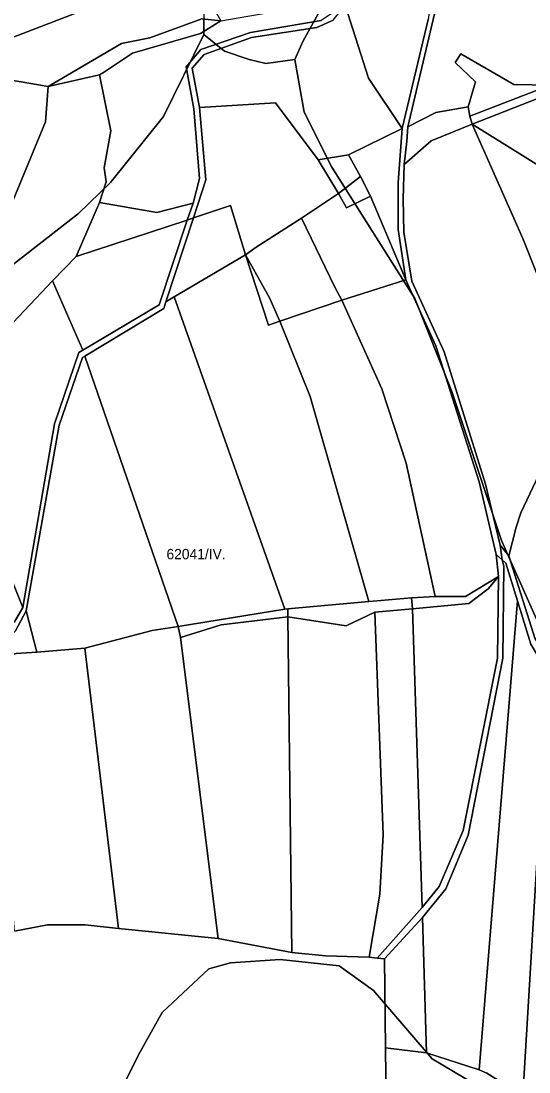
# Model space of a CAD drawing. Extents: x -521261 to -517465, y -1182764 to -1179456.
# Drawn here: x -519763 to -519518, y -1182060 to -1181552 of the extents above; entities that cross this region are included whole.
import ezdxf

# ---------------------------------------------------------------- set-up
doc = ezdxf.new("R2010")
doc.units = 0
for name, color, linetype in [('95560013', 7, 'Continuous'), ('95610013', 7, 'Continuous'), ('95640013', 7, 'Continuous'), ('95660013', 7, 'Continuous')]:
    doc.layers.add(name, color=color, linetype=linetype)

msp = doc.modelspace()

# ---------------------------------------------------------------- linework, layer by layer
at = {"layer": '95560013'}
for points in [[(-519680.38, -1181522.18), (-519678.62, -1181526.13), (-519766.59, -1181560.03), (-519806.34, -1181557.48), (-519812.18, -1181559.97), (-519819.03, -1181562.34), (-519820.94, -1181549.11), (-519799.35, -1181551.07), (-519780.96, -1181551.7), (-519759.56, -1181546.55), (-519747.84, -1181543.58), (-519734.21, -1181538), (-519696.97, -1181527.88)], [(-519679.91, -1181647.56), (-519662.1, -1181641.54), (-519654.76, -1181665.48), (-519689.23, -1181685.68), (-519693.3, -1181688.1)], [(-519679.91, -1181647.56), (-519693.3, -1181688.1), (-519694.25, -1181691.29), (-519732.44, -1181714.35), (-519733.56, -1181715), (-519744.8, -1181747.67), (-519760.86, -1181837.52), (-519766.01, -1181847.11), (-519783.93, -1181864.52), (-519787.23, -1181865.65), (-519792.03, -1181867.82), (-519766.42, -1181842.85), (-519762.47, -1181835.83), (-519747.07, -1181747.06), (-519735.36, -1181712.66), (-519733.42, -1181711.55), (-519696.55, -1181689.51), (-519683.02, -1181648.68)], [(-519683.02, -1181648.68), (-519696.55, -1181689.51), (-519733.42, -1181711.55), (-519748.09, -1181677.97), (-519736.69, -1181666.21)], [(-519654.76, -1181665.48), (-519643.73, -1181699.41), (-519638.17, -1181697.44), (-519623.58, -1181733.81), (-519595.24, -1181832.9), (-519634.35, -1181836.49), (-519635.8, -1181836.66), (-519689.23, -1181685.68)], [(-519748.09, -1181677.97), (-519733.42, -1181711.55), (-519735.36, -1181712.66), (-519747.07, -1181747.06), (-519762.47, -1181835.83), (-519785.74, -1181777.95), (-519807.95, -1181734.53), (-519769.78, -1181700.98)], [(-519608.18, -1181687.27), (-519577.34, -1181677.47), (-519562.88, -1181709.42), (-519541.79, -1181775.11), (-519533.67, -1181810.31), (-519532.44, -1181820.87), (-519548.5, -1181830.55), (-519563.13, -1181830.46), (-519577.15, -1181766.06), (-519588.95, -1181730.16)], [(-519689.23, -1181685.68), (-519635.8, -1181836.66), (-519687.27, -1181844.99), (-519732.44, -1181714.35), (-519694.25, -1181691.29), (-519693.3, -1181688.1)], [(-519638.17, -1181697.44), (-519608.18, -1181687.27), (-519588.95, -1181730.16), (-519577.15, -1181766.06), (-519563.13, -1181830.46), (-519574.5, -1181831.25), (-519593.02, -1181832.73), (-519595.24, -1181832.9), (-519623.58, -1181733.81)], [(-519733.56, -1181715), (-519732.44, -1181714.35), (-519687.27, -1181844.99), (-519699.9, -1181846.96), (-519732.49, -1181855.46), (-519755.59, -1181857.41), (-519760.86, -1181837.52), (-519744.8, -1181747.67)], [(-519807.95, -1181734.53), (-519785.74, -1181777.95), (-519762.47, -1181835.83), (-519766.42, -1181842.85), (-519792.03, -1181867.82), (-519816.1, -1181875.42), (-519863.92, -1181760.51)], [(-519530.74, -1181812.82), (-519530, -1181815.87), (-519530.37, -1181860.39), (-519547.1, -1181945.82), (-519558, -1181971.8), (-519569.21, -1181985.7), (-519587.58, -1182005.62), (-519591.13, -1182005.4), (-519569.48, -1181980.84), (-519561.19, -1181970.73), (-519549.62, -1181943.63), (-519533.07, -1181860.26), (-519532.44, -1181820.87), (-519533.67, -1181810.31)], [(-519529.03, -1181814.46), (-519523.41, -1181832.63), (-519541.91, -1182059.26), (-519567.33, -1182051.07), (-519569.21, -1181985.7), (-519558, -1181971.8), (-519547.1, -1181945.82), (-519530.37, -1181860.39), (-519530, -1181815.87), (-519530.74, -1181812.82)], [(-519532.44, -1181820.87), (-519537.44, -1181826.81), (-519546.83, -1181833.97), (-519574.08, -1181836.42), (-519574.5, -1181831.25), (-519563.13, -1181830.46), (-519548.5, -1181830.55)], [(-519532.44, -1181820.87), (-519533.07, -1181860.26), (-519549.62, -1181943.63), (-519561.19, -1181970.73), (-519569.48, -1181980.84), (-519574.08, -1181836.42), (-519546.83, -1181833.97), (-519537.44, -1181826.81)], [(-519593.02, -1181832.73), (-519574.5, -1181831.25), (-519574.08, -1181836.42), (-519592.35, -1181838.15), (-519606.06, -1181844.65), (-519634.35, -1181840.4), (-519634.35, -1181836.49), (-519595.24, -1181832.9)], [(-519516.92, -1181853.55), (-519508.53, -1181867.8), (-519520.78, -1182071.93), (-519538.16, -1182060.97), (-519541.91, -1182059.26), (-519523.41, -1181832.63)], [(-519766.01, -1181847.11), (-519760.86, -1181837.52), (-519755.59, -1181857.41), (-519765.71, -1181858.12), (-519783.93, -1181864.52)], [(-519635.8, -1181836.66), (-519634.35, -1181836.49), (-519634.35, -1181840.4), (-519666.57, -1181844.27), (-519686.27, -1181850.34), (-519687.27, -1181844.99)], [(-519666.57, -1181844.27), (-519634.35, -1181840.4), (-519632.39, -1182002.52), (-519668.08, -1181995.79), (-519686.27, -1181850.34)], [(-519606.06, -1181844.65), (-519592.35, -1181838.15), (-519588.2, -1181945.64), (-519589.8, -1181974.4), (-519595.04, -1182004.9), (-519616.07, -1182004.27), (-519632.39, -1182002.52), (-519634.35, -1181840.4)], [(-519574.08, -1181836.42), (-519569.48, -1181980.84), (-519591.13, -1182005.4), (-519595.04, -1182004.9), (-519589.8, -1181974.4), (-519588.2, -1181945.64), (-519592.35, -1181838.15)], [(-519699.9, -1181846.96), (-519687.27, -1181844.99), (-519686.27, -1181850.34), (-519668.08, -1181995.79), (-519716.14, -1181990.99), (-519732.49, -1181855.46)], [(-519755.59, -1181857.41), (-519732.49, -1181855.46), (-519716.14, -1181990.99), (-519732.22, -1181989.26), (-519750.52, -1181989.15), (-519766.51, -1181992.23), (-519768.6, -1181965.95), (-519779.45, -1181903.21), (-519787.23, -1181865.65), (-519783.93, -1181864.52), (-519765.71, -1181858.12)], [(-519487.9, -1181902.3), (-519501.15, -1182074.26), (-519520.78, -1182071.93), (-519508.53, -1181867.8)], [(-519587.58, -1182005.62), (-519569.21, -1181985.7), (-519567.33, -1182051.07), (-519587.21, -1182048.68)], [(-519587.21, -1182048.68), (-519567.33, -1182051.07), (-519541.91, -1182059.26), (-519538.16, -1182060.97), (-519520.78, -1182071.93), (-519539.14, -1182070.29), (-519569.64, -1182074.9), (-519574.23, -1182075.58), (-519574.86, -1182083.63), (-519575.95, -1182097.41), (-519585.88, -1182094.5), (-519586.88, -1182076.07)]]:
    msp.add_lwpolyline(points, close=True, dxfattribs=at)
msp.add_lwpolyline([(-519766.51, -1181992.23), (-519750.52, -1181989.15), (-519732.22, -1181989.26), (-519716.14, -1181990.99), (-519668.08, -1181995.79), (-519632.39, -1182002.52), (-519616.07, -1182004.27), (-519595.04, -1182004.9), (-519591.13, -1182005.4), (-519587.58, -1182005.62), (-519587.21, -1182048.68), (-519586.88, -1182076.07)], dxfattribs=at)
at = {"layer": '95610013'}
for points in [[(-519509.72, -1181489.33), (-519469.92, -1181557.79), (-519456.65, -1181563.71), (-519459.18, -1181565.12), (-519493.06, -1181564.31), (-519488.66, -1181575.99), (-519507.62, -1181583.34), (-519525.03, -1181583.04), (-519550.78, -1181568.23), (-519553.52, -1181572.42), (-519543.61, -1181581.76), (-519547.14, -1181593.89), (-519562.84, -1181596.65), (-519576.31, -1181603.51), (-519563.51, -1181548.93), (-519560.91, -1181533.55), (-519560.59, -1181527.09), (-519562.54, -1181512.84), (-519534.8, -1181505.37)], [(-519563.51, -1181529.49), (-519566.46, -1181551.62), (-519579.08, -1181604.33), (-519595.33, -1181580.07), (-519606.57, -1181544.76), (-519590.4, -1181540.7), (-519582.82, -1181535.82), (-519565.36, -1181513.85)], [(-519678.62, -1181526.13), (-519673.88, -1181539.64), (-519666.73, -1181552.31), (-519675.86, -1181551.28), (-519701.01, -1181560.52), (-519714.71, -1181563.35), (-519750.21, -1181584.11), (-519816.71, -1181572.59), (-519812.18, -1181559.97), (-519806.34, -1181557.48), (-519766.59, -1181560.03)], [(-519608.88, -1181542.36), (-519611.93, -1181548.02), (-519618.29, -1181552.11), (-519652.35, -1181557.92), (-519676.31, -1181566.13), (-519683.42, -1181574.5), (-519679.84, -1181594.88), (-519677.08, -1181628.55), (-519680.02, -1181640.51), (-519697.65, -1181644.91), (-519725.3, -1181640.16), (-519722.14, -1181630.1), (-519723.1, -1181623.37), (-519719.9, -1181605.52), (-519725.37, -1181578.38), (-519723.42, -1181577.22), (-519709.37, -1181567.9), (-519676.51, -1181558.49), (-519666.73, -1181552.31)], [(-519606.57, -1181544.76), (-519595.33, -1181580.07), (-519579.08, -1181604.33), (-519605.01, -1181617.05), (-519619.68, -1181619.56), (-519640.3, -1181591.88), (-519677.07, -1181594.2), (-519680.51, -1181575.15), (-519674.82, -1181568.57), (-519651.84, -1181560.32), (-519620.27, -1181555.53), (-519612.49, -1181551.99)], [(-519675.86, -1181551.28), (-519666.73, -1181552.31), (-519676.51, -1181558.49), (-519709.37, -1181567.9), (-519723.42, -1181577.22), (-519725.37, -1181578.38), (-519750.21, -1181584.11), (-519714.71, -1181563.35), (-519701.01, -1181560.52)], [(-519553.52, -1181572.42), (-519550.78, -1181568.23), (-519525.03, -1181583.04), (-519507.62, -1181583.34), (-519546.36, -1181598.36), (-519547.14, -1181593.89), (-519543.61, -1181581.76)], [(-519816.71, -1181572.59), (-519750.21, -1181584.11), (-519751.5, -1181601.06), (-519770.09, -1181646.33), (-519778.31, -1181659.21), (-519810.79, -1181685), (-519827.1, -1181695.28), (-519832.55, -1181698.75), (-519856.07, -1181708.81), (-519845.05, -1181651.51)], [(-519478.73, -1181576.14), (-519474.01, -1181575.19), (-519466.37, -1181576.22), (-519462.75, -1181578.47), (-519449.37, -1181594.38), (-519460.32, -1181602.95), (-519490.67, -1181627.18), (-519486.95, -1181633.64), (-519492.65, -1181634.89), (-519545.26, -1181602.19), (-519497.59, -1181583.52), (-519485.75, -1181583.73), (-519487.34, -1181579.51)], [(-519750.21, -1181584.11), (-519725.37, -1181578.38), (-519719.9, -1181605.52), (-519723.1, -1181623.37), (-519722.14, -1181630.1), (-519725.3, -1181640.16), (-519736.69, -1181666.21), (-519748.09, -1181677.97), (-519769.78, -1181700.98), (-519807.95, -1181734.53), (-519863.92, -1181760.51), (-519856.07, -1181708.81), (-519832.55, -1181698.75), (-519827.1, -1181695.28), (-519810.79, -1181685), (-519778.31, -1181659.21), (-519770.09, -1181646.33), (-519751.5, -1181601.06)], [(-519640.3, -1181591.88), (-519619.68, -1181619.56), (-519609.79, -1181635.73), (-519627.77, -1181647.74), (-519649.61, -1181661.63), (-519654.76, -1181665.48), (-519662.1, -1181641.54), (-519679.91, -1181647.56), (-519673.89, -1181629.09), (-519677.07, -1181594.2)], [(-519579.08, -1181604.33), (-519580.98, -1181630.38), (-519580.97, -1181653.09), (-519577.34, -1181677.47), (-519594.39, -1181637.09), (-519599.23, -1181627.57), (-519605.01, -1181617.05)], [(-519565.03, -1181610.38), (-519545.26, -1181602.19), (-519520.75, -1181657.44), (-519505.86, -1181694.79), (-519498.2, -1181718.82), (-519509.68, -1181742.43), (-519508.54, -1181762.3), (-519521.69, -1181790.12), (-519524.04, -1181797.09), (-519527.59, -1181810.9), (-519531.67, -1181805.67), (-519538.74, -1181776.21), (-519558.85, -1181712.23), (-519574.34, -1181678.1), (-519578.35, -1181654.41), (-519578.54, -1181638.45), (-519578.07, -1181621.73)], [(-519492.65, -1181634.89), (-519486.95, -1181633.64), (-519457.1, -1181680.7), (-519476.47, -1181700.33), (-519498.2, -1181718.82), (-519505.86, -1181694.79), (-519520.75, -1181657.44), (-519545.26, -1181602.19)], [(-519605.01, -1181617.05), (-519599.23, -1181627.57), (-519609.79, -1181635.73), (-519619.68, -1181619.56)], [(-519609.79, -1181635.73), (-519599.23, -1181627.57), (-519594.39, -1181637.09), (-519605.93, -1181642.66)], [(-519594.39, -1181637.09), (-519577.34, -1181677.47), (-519608.18, -1181687.27), (-519611.58, -1181681.03), (-519627.77, -1181647.74), (-519609.79, -1181635.73), (-519605.93, -1181642.66)], [(-519697.65, -1181644.91), (-519680.02, -1181640.51), (-519683.02, -1181648.68), (-519736.69, -1181666.21), (-519725.3, -1181640.16)], [(-519627.77, -1181647.74), (-519611.58, -1181681.03), (-519608.18, -1181687.27), (-519638.17, -1181697.44), (-519643.15, -1181686.22), (-519654.76, -1181665.48), (-519649.61, -1181661.63)], [(-519643.15, -1181686.22), (-519638.17, -1181697.44), (-519643.73, -1181699.41), (-519654.76, -1181665.48)], [(-519464.34, -1181702.69), (-519450.65, -1181691.27), (-519407.91, -1181758.76), (-519457.7, -1181801.62), (-519514.79, -1181851.2), (-519527.59, -1181810.9), (-519524.04, -1181797.09), (-519521.69, -1181790.12), (-519508.54, -1181762.3), (-519501.06, -1181757.42), (-519491.57, -1181735.94), (-519489.97, -1181728.17)]]:
    msp.add_lwpolyline(points, close=True, dxfattribs=at)
at = {"layer": '95640013'}
for points in [[(-519563.51, -1181548.93), (-519576.31, -1181603.51), (-519576.86, -1181610.44), (-519578.07, -1181621.73), (-519578.54, -1181638.45), (-519578.35, -1181654.41), (-519574.34, -1181678.1), (-519558.85, -1181712.23), (-519538.74, -1181776.21), (-519531.67, -1181805.67), (-519530.74, -1181812.82), (-519533.67, -1181810.31), (-519541.79, -1181775.11), (-519562.88, -1181709.42), (-519577.34, -1181677.47), (-519580.97, -1181653.09), (-519580.98, -1181630.38), (-519579.08, -1181604.33), (-519566.46, -1181551.62)], [(-519612.49, -1181551.99), (-519620.27, -1181555.53), (-519651.84, -1181560.32), (-519674.82, -1181568.57), (-519680.51, -1181575.15), (-519677.07, -1181594.2), (-519673.89, -1181629.09), (-519679.91, -1181647.56), (-519683.02, -1181648.68), (-519680.02, -1181640.51), (-519677.08, -1181628.55), (-519679.84, -1181594.88), (-519683.42, -1181574.5), (-519676.31, -1181566.13), (-519652.35, -1181557.92), (-519618.29, -1181552.11)]]:
    msp.add_lwpolyline(points, dxfattribs=at)
for points in [[(-519468.92, -1181569.73), (-519461.85, -1181571.29), (-519457.38, -1181574.5), (-519444.05, -1181589.92), (-519449.37, -1181594.38), (-519462.75, -1181578.47), (-519466.37, -1181576.22), (-519474.01, -1181575.19), (-519478.73, -1181576.14), (-519487.34, -1181579.51), (-519497.59, -1181583.52), (-519545.26, -1181602.19), (-519546.36, -1181598.36), (-519507.62, -1181583.34), (-519488.66, -1181575.99), (-519474.47, -1181570.5)], [(-519547.14, -1181593.89), (-519546.36, -1181598.36), (-519545.26, -1181602.19), (-519565.03, -1181610.38), (-519578.07, -1181621.73), (-519576.86, -1181610.44), (-519576.31, -1181603.51), (-519562.84, -1181596.65)], [(-519531.67, -1181805.67), (-519527.59, -1181810.9), (-519514.79, -1181851.2), (-519465.56, -1181934.8), (-519464.46, -1181937.6), (-519475.35, -1182094.14), (-519478.73, -1182090.66), (-519467.21, -1181936.45), (-519487.9, -1181902.3), (-519508.53, -1181867.8), (-519516.92, -1181853.55), (-519523.41, -1181832.63), (-519529.03, -1181814.46), (-519530.74, -1181812.82)]]:
    msp.add_lwpolyline(points, close=True, dxfattribs=at)
at = {"layer": '95660013'}
for points in [[(-519774.62, -1181212.01), (-519750.87, -1181207.64), (-519728.68, -1181193.73), (-519707.46, -1181181.92), (-519697.73, -1181178.01), (-519707, -1181243.5), (-519710.5, -1181283.5), (-519710.5, -1181356), (-519702, -1181410), (-519696.5, -1181441.5), (-519675.5, -1181504.5), (-519674, -1181518), (-519675, -1181551.5), (-519675, -1181559), (-519694.5, -1181598.5), (-519720, -1181630.5), (-519735.5, -1181645.5), (-519871, -1181751)], [(-519618, -1181546), (-519627, -1181562), (-519631, -1181571), (-519645, -1181573), (-519653, -1181571), (-519665, -1181567), (-519675, -1181559), (-519675, -1181551.5)], [(-519476, -1182064.5), (-519466, -1182000), (-519473.5, -1181961), (-519499, -1181875.5), (-519531, -1181803.5), (-519555, -1181731.5), (-519573, -1181686.5), (-519613, -1181623), (-519626.5, -1181596.5), (-519631, -1181571), (-519627, -1181562), (-519618, -1181546)], [(-519871, -1181751), (-519735.5, -1181645.5), (-519720, -1181630.5), (-519694.5, -1181598.5), (-519675, -1181559), (-519665, -1181567), (-519653, -1181571), (-519645, -1181573), (-519631, -1181571), (-519626.5, -1181596.5), (-519613, -1181623), (-519573, -1181686.5), (-519555, -1181731.5), (-519531, -1181803.5), (-519499, -1181875.5), (-519473.5, -1181961), (-519466, -1182000), (-519476, -1182064.5)], [(-519719, -1182077.5), (-519706.5, -1182052), (-519695, -1182031.5), (-519672.5, -1182010.5), (-519662, -1182007.5), (-519638, -1182006), (-519609.5, -1182009), (-519593, -1182021), (-519564.5, -1182054), (-519525, -1182077.5)], [(-519525, -1182077.5), (-519564.5, -1182054), (-519593, -1182021), (-519609.5, -1182009), (-519638, -1182006), (-519662, -1182007.5), (-519672.5, -1182010.5), (-519695, -1182031.5), (-519706.5, -1182052), (-519719, -1182077.5)]]:
    msp.add_lwpolyline(points, dxfattribs=at)

# ---------------------------------------------------------------- texts
msp.add_text('62041/IV.', height=5, rotation=0, dxfattribs=at).set_placement((-519693, -1181812.55))

doc.saveas('drawing.dxf')
